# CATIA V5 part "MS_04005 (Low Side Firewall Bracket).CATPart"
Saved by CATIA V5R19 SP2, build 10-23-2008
Part number: MS_04005 (Low Side Firewall Bracket)
Bounding box of the stored display mesh (mm): x -1146.869 to 0, y -234.325 to 0, z -93.973 to 0
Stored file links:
  D:\EPSA\GIT\ELIZ-2022\01 - Maquette CATIA\MS_Miscellanous_Finish_Assembly\MS_A0400 (Firewall)\MS_04005 (Low Side Firewall Bracket).CATPart
  D:\EPSA\GIT\ELIZ-2022\01 - Maquette CATIA\MS_Miscellanous_Finish_Assembly\MS_A0400 (Firewall)\MS_A0400 (FireWall).CATProduct
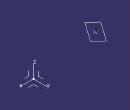
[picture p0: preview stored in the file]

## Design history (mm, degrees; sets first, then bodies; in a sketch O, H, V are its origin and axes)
AxisSystem1: origin (0, 0, 0), X (1, 0, 0), Y (0, 1, 0), Z (0, 0, 1)
Set1
  Point1: type OnCurve, Support DatumCurve1, Length 489.226
  Plane1: type Normal, Curve DatumCurve1, RefPoint Point1
  Sketch1 on Plane1, origin (-1142.8705, -200.5753, -87.9446), H (0.1729, -0.9849, 0), V (-0.0744, -0.0131, 0.9971)
    circle A1 centre (34.3462, -6.0462) radius 14
    point P1 (34.3462, -6.0462)
    reference projected point E1 (34.3462, -6.0462) from Point1
    radius A1 = 14
    coincidence: P1 E1
Set2
  DatumCurve1: linked copy from another document
  Plane2: linked copy from another document
  DatumSurface1 to DatumSurface3: linked copy from another document
Body1 (main body)
  Pad1: profile Sketch1, direction (-0.9821, -0.1724, -0.0756), length 30, opposite side length 30
  Point2: type OnSurface, Support face of Pad1 from Sketch1.A1, Length 10.962, Direction (-0.0367, 0.9244, -0.3797)
  Plane3: type Tangent, Support DatumSurface1, RefPoint Point2
  Line1: type PtDir, RefPoint Point2, Direction DatumCurve1, Start -25, End 23
Body2
  Sketch2 on face of DatumSurface3, origin (3.8523, -19.9899, -4.4703), H (-0.9819, -0.1892, 0), V (0.0406, -0.2106, 0.9767)
    reference intersected line E1 through (1160.1769, -90.0399) direction (0.0774, 0.997) from Plane1
    arc A1 centre (1162.3034, -62.6394) radius 7 from (1162.8451, -55.6603) to (1155.3244, -62.0977) ccw
    point P3 (1162.3034, -62.6394)
    point P4 (1162.8451, -55.6603)
    point P5 (1155.3244, -62.0977)
    line L1 (1155.3244, -62.0977) -> (1153.3126, -88.0198)
    point P6 (1153.3126, -88.0198)
    line L2 (1153.3126, -88.0198) -> (1160.2917, -88.5614)
    point P7 (1160.2917, -88.5614)
    reference intersected line E2 (1190.2017, -90.8827) -> (1130.3816, -86.2401) from face of Pad1 from Sketch1.A1
    circle A2 centre (1162.3034, -62.6394) radius 1.7
    point P10 (1160.2917, -88.5614)
    point P11 (1167.2707, -89.103)
    line L3 (1167.2707, -89.103) -> (1160.2917, -88.5614)
    point P12 (1169.2824, -63.181)
    line L4 (1169.2824, -63.181) -> (1167.2707, -89.103)
    point P13 (1162.8451, -55.6603)
    arc A3 centre (1162.3034, -62.6394) radius 7 from (1162.8451, -55.6603) to (1169.2824, -63.181) cw
    radius A1 = 7
    length L1 = 26
    radius A2 = 1.7
    coincidence: P3 E1, P4 E1, P7 E1, L2 E2, P4 P13, P7 P10
    tangency: L1 A1
    perpendicularity: L2 L1
    symmetry: P7 P10 E1, P6 P11 E1, L2 L3 E1, P5 P12 E1, L1 L4 E1, P4 P13 E1, A1 A3 E1
  Pad2: profile Sketch2, direction (0.1848, -0.9591, -0.2145), length 1.5
  Sketch3 on end face of Pad2, origin (4.1295, -21.4285, -4.792), H (0.9819, 0.1892, 0), V (0.0406, -0.2106, 0.9767)
    intersected line E1 (-1130.8694, -79.9543) -> (-1190.6896, -84.5968) from face of Pad1 from Sketch1.A1
    intersected line E2 (-1129.8938, -92.526) -> (-1189.7139, -97.1685) from face of Pad1 from Sketch1.A1
    point P3 (-1129.8938, -92.526)
    line L1 (-1190.6896, -84.5968) -> (-1189.7139, -97.1685)
    line L2 (-1130.8694, -79.9543) -> (-1129.8938, -92.526)
    point P5 (-1129.8938, -92.526)
    perpendicularity: L1 E1
    parallelism: L2 L1
    coincidence: P3 P5
  Pocket1: profile Sketch3, direction (-0.1848, 0.9591, 0.2145), up to start face of Pad2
